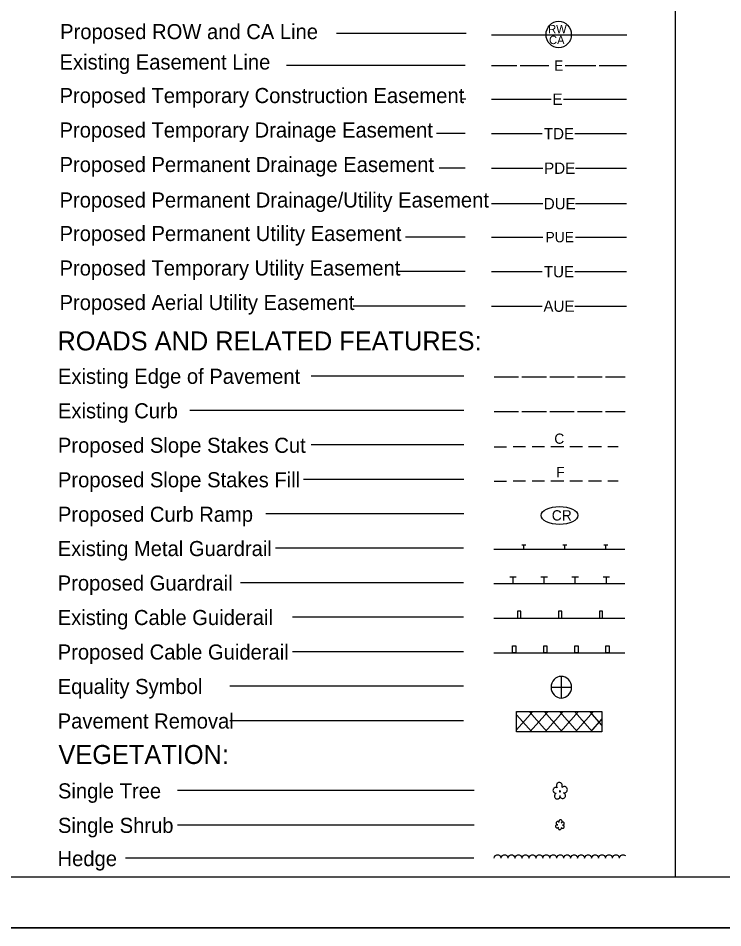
# Model space of a CAD drawing. Extents: x 2025847 to 2026166, y 840763 to 840870.
# Drawn here: x 2026059.3 to 2026094.71, y 840778.42 to 840824.12 of the extents above; entities that cross this region are included whole.
import ezdxf

# ---------------------------------------------------------------- set-up
doc = ezdxf.new("R2010")
doc.units = 0
for name, color, linetype in [('P_RDY_Easement_Permanent_Drainage_Utility', 7, 'Continuous'), ('P_RDY_WCC_CELL', 7, 'Continuous'), ('Sheet_Plan', 7, 'Continuous'), ('Sheet_Plot_Border_Outside_CELL', 7, 'Continuous'), ('Sheet_Symbology', 7, 'Continuous'), ('z - Construction', 7, 'Continuous')]:
    doc.layers.add(name, color=color, linetype=linetype)

msp = doc.modelspace()

# ---------------------------------------------------------------- linework, layer by layer
at = {"layer": 'P_RDY_Easement_Permanent_Drainage_Utility'}
for p, q in [((2026083.088, 840814.806), (2026085.664, 840814.806)), ((2026087.311, 840814.806), (2026089.879, 840814.806))]:
    msp.add_line(p, q, dxfattribs=at)
at = {"layer": 'P_RDY_WCC_CELL'}
msp.add_ellipse((2026086.504, 840799.138), major_axis=(0.923, 0), ratio=0.486807, dxfattribs=at)
at = {"layer": 'Sheet_Plan'}
msp.add_line((2026024.668, 840780.981), (2026164.546, 840780.981), dxfattribs=at)
at = {"layer": 'Sheet_Plot_Border_Outside_CELL'}
msp.add_lwpolyline([(2026023.879, 840870.085), (2026165.546, 840870.085), (2026165.546, 840778.419), (2026023.879, 840778.419)], close=True, dxfattribs=at)
at = {"layer": 'Sheet_Symbology'}
for p, q in [((2026081.82, 840823.354), (2026075.288, 840823.354)), ((2026083.089, 840823.287), (2026089.88, 840823.287)), ((2026081.768, 840821.741), (2026072.775, 840821.741)), ((2026083.088, 840821.741), (2026084.365, 840821.741)), ((2026084.529, 840821.741), (2026085.97, 840821.741)), ((2026086.793, 840821.741), (2026088.336, 840821.741)), ((2026088.501, 840821.741), (2026089.879, 840821.741)), ((2026081.8, 840820.055), (2026081.593, 840820.055)), ((2026083.088, 840820.055), (2026083.303, 840820.055)), ((2026083.303, 840820.055), (2026086.081, 840820.055)), ((2026086.698, 840820.055), (2026089.477, 840820.055)), ((2026089.477, 840820.055), (2026089.879, 840820.055)), ((2026081.768, 840818.322), (2026080.328, 840818.322)), ((2026083.088, 840818.322), (2026083.364, 840818.322)), ((2026083.364, 840818.322), (2026085.627, 840818.322)), ((2026087.274, 840818.322), (2026089.537, 840818.322)), ((2026089.537, 840818.322), (2026089.879, 840818.322)), ((2026081.768, 840816.589), (2026080.45, 840816.589)), ((2026083.088, 840816.589), (2026083.401, 840816.589)), ((2026083.401, 840816.589), (2026085.664, 840816.589)), ((2026087.311, 840816.589), (2026089.574, 840816.589)), ((2026089.574, 840816.589), (2026089.879, 840816.589)), ((2026081.768, 840813.122), (2026078.771, 840813.122)), ((2026083.088, 840813.122), (2026083.404, 840813.122)), ((2026083.404, 840813.122), (2026085.667, 840813.122)), ((2026087.314, 840813.122), (2026089.577, 840813.122)), ((2026089.577, 840813.122), (2026089.879, 840813.122)), ((2026081.768, 840811.389), (2026078.3, 840811.389)), ((2026083.088, 840811.389), (2026083.364, 840811.389)), ((2026083.364, 840811.389), (2026085.627, 840811.389)), ((2026087.274, 840811.389), (2026089.537, 840811.389)), ((2026089.537, 840811.389), (2026089.879, 840811.389)), ((2026081.768, 840809.656), (2026076.133, 840809.656)), ((2026083.088, 840809.656), (2026083.364, 840809.656)), ((2026083.364, 840809.656), (2026085.627, 840809.656)), ((2026087.274, 840809.656), (2026089.537, 840809.656)), ((2026089.537, 840809.656), (2026089.879, 840809.656)), ((2026081.689, 840806.145), (2026074.014, 840806.145)), ((2026083.214, 840806.095), (2026084.449, 840806.095)), ((2026084.614, 840806.095), (2026085.848, 840806.095)), ((2026086.013, 840806.095), (2026087.248, 840806.095)), ((2026087.413, 840806.095), (2026088.647, 840806.095)), ((2026088.812, 840806.095), (2026089.8, 840806.095)), ((2026081.689, 840804.412), (2026067.93, 840804.412)), ((2026083.214, 840804.362), (2026084.449, 840804.362)), ((2026084.614, 840804.362), (2026085.848, 840804.362)), ((2026086.013, 840804.362), (2026087.248, 840804.362)), ((2026087.413, 840804.362), (2026088.647, 840804.362)), ((2026088.812, 840804.362), (2026089.8, 840804.362)), ((2026081.689, 840802.679), (2026074.018, 840802.679)), ((2026083.214, 840802.588), (2026083.84, 840802.588)), ((2026084.803, 840802.588), (2026084.182, 840802.588)), ((2026085.75, 840802.588), (2026085.124, 840802.588)), ((2026086.717, 840802.588), (2026086.075, 840802.588)), ((2026087.659, 840802.588), (2026087.022, 840802.588)), ((2026088.61, 840802.588), (2026087.964, 840802.588)), ((2026089.458, 840802.588), (2026088.931, 840802.588)), ((2026081.689, 840800.946), (2026073.644, 840800.946)), ((2026083.214, 840800.855), (2026083.84, 840800.855)), ((2026084.803, 840800.855), (2026084.182, 840800.855)), ((2026085.75, 840800.855), (2026085.124, 840800.855)), ((2026086.717, 840800.855), (2026086.075, 840800.855)), ((2026087.659, 840800.855), (2026087.022, 840800.855)), ((2026088.61, 840800.855), (2026087.964, 840800.855)), ((2026089.458, 840800.855), (2026088.931, 840800.855)), ((2026081.689, 840799.213), (2026071.735, 840799.213)), ((2026081.676, 840797.49), (2026072.223, 840797.49)), ((2026083.201, 840797.441), (2026089.787, 840797.441)), ((2026084.612, 840797.657), (2026084.818, 840797.657)), ((2026084.715, 840797.441), (2026084.715, 840797.657)), ((2026086.67, 840797.657), (2026086.876, 840797.657)), ((2026086.773, 840797.441), (2026086.773, 840797.657)), ((2026088.728, 840797.657), (2026088.934, 840797.657)), ((2026088.831, 840797.441), (2026088.831, 840797.657)), ((2026084.002, 840796.05), (2026084.331, 840796.05)), ((2026084.167, 840795.708), (2026084.167, 840796.05)), ((2026085.566, 840796.05), (2026085.895, 840796.05)), ((2026085.731, 840795.708), (2026085.731, 840796.05)), ((2026087.13, 840796.05), (2026087.459, 840796.05)), ((2026087.295, 840795.708), (2026087.295, 840796.05)), ((2026088.694, 840796.05), (2026089.023, 840796.05)), ((2026088.859, 840795.708), (2026088.859, 840796.05)), ((2026081.676, 840795.757), (2026070.462, 840795.757)), ((2026089.787, 840795.708), (2026083.201, 840795.708)), ((2026081.676, 840794.024), (2026073.091, 840794.024)), ((2026083.201, 840793.975), (2026089.787, 840793.975)), ((2026081.676, 840792.291), (2026073.091, 840792.291)), ((2026083.201, 840792.242), (2026089.787, 840792.242)), ((2026086.595, 840791.049), (2026086.595, 840790.508)), ((2026081.676, 840790.558), (2026069.936, 840790.558)), ((2026086.081, 840790.508), (2026086.595, 840790.508)), ((2026086.595, 840790.508), (2026086.595, 840789.966)), ((2026086.595, 840790.508), (2026087.109, 840790.508)), ((2026084.35, 840789.284), (2026088.639, 840789.284)), ((2026084.35, 840788.27), (2026084.35, 840789.284)), ((2026084.35, 840789.232), (2026084.395, 840789.284)), ((2026084.35, 840788.369), (2026085.161, 840789.284)), ((2026085.877, 840788.27), (2026084.971, 840789.284)), ((2026085.021, 840788.27), (2026085.926, 840789.284)), ((2026086.638, 840788.27), (2026085.737, 840789.284)), ((2026085.782, 840788.27), (2026086.692, 840789.284)), ((2026087.404, 840788.27), (2026086.498, 840789.284)), ((2026086.548, 840788.27), (2026087.453, 840789.284)), ((2026088.169, 840788.27), (2026087.26, 840789.284)), ((2026087.313, 840788.27), (2026088.215, 840789.284)), ((2026088.639, 840788.595), (2026088.025, 840789.284)), ((2026088.639, 840789.284), (2026088.639, 840788.27)), ((2026081.676, 840788.825), (2026069.936, 840788.825)), ((2026085.111, 840788.27), (2026084.35, 840789.128)), ((2026088.075, 840788.27), (2026088.639, 840788.902)), ((2026088.639, 840788.27), (2026084.35, 840788.27)), ((2026082.218, 840785.312), (2026067.308, 840785.312)), ((2026082.218, 840783.579), (2026067.308, 840783.579)), ((2026082.196, 840781.911), (2026064.688, 840781.911)), ((2026083.216, 840781.911), (2026083.241, 840781.993)), ((2026083.241, 840781.993), (2026083.29, 840782.049)), ((2026083.29, 840782.049), (2026083.356, 840782.088)), ((2026083.356, 840782.088), (2026083.434, 840782.088)), ((2026083.434, 840782.088), (2026083.5, 840782.045)), ((2026083.5, 840782.045), (2026083.545, 840781.989)), ((2026083.545, 840781.989), (2026083.562, 840781.915)), ((2026083.566, 840781.911), (2026083.59, 840781.993)), ((2026083.59, 840781.993), (2026083.64, 840782.049)), ((2026083.64, 840782.049), (2026083.706, 840782.088)), ((2026083.706, 840782.088), (2026083.784, 840782.088)), ((2026083.784, 840782.088), (2026083.85, 840782.045)), ((2026083.85, 840782.045), (2026083.895, 840781.989)), ((2026083.895, 840781.989), (2026083.911, 840781.915)), ((2026083.916, 840781.911), (2026083.94, 840781.993)), ((2026083.94, 840781.993), (2026083.99, 840782.049)), ((2026083.99, 840782.049), (2026084.056, 840782.088)), ((2026084.056, 840782.088), (2026084.134, 840782.088)), ((2026084.134, 840782.088), (2026084.2, 840782.045)), ((2026084.2, 840782.045), (2026084.245, 840781.989)), ((2026084.245, 840781.989), (2026084.261, 840781.915)), ((2026084.265, 840781.911), (2026084.29, 840781.993)), ((2026084.29, 840781.993), (2026084.339, 840782.049)), ((2026084.339, 840782.049), (2026084.405, 840782.088)), ((2026084.405, 840782.088), (2026084.484, 840782.088)), ((2026084.484, 840782.088), (2026084.549, 840782.045)), ((2026084.549, 840782.045), (2026084.595, 840781.989)), ((2026084.595, 840781.989), (2026084.611, 840781.915)), ((2026084.615, 840781.911), (2026084.64, 840781.993)), ((2026084.64, 840781.993), (2026084.689, 840782.049)), ((2026084.689, 840782.049), (2026084.755, 840782.088)), ((2026084.755, 840782.088), (2026084.833, 840782.088)), ((2026084.833, 840782.088), (2026084.899, 840782.045)), ((2026084.899, 840782.045), (2026084.945, 840781.989)), ((2026084.945, 840781.989), (2026084.961, 840781.915)), ((2026084.965, 840781.911), (2026084.99, 840781.993)), ((2026084.99, 840781.993), (2026085.039, 840782.049)), ((2026085.039, 840782.049), (2026085.105, 840782.088)), ((2026085.105, 840782.088), (2026085.183, 840782.088)), ((2026085.183, 840782.088), (2026085.249, 840782.045)), ((2026085.249, 840782.045), (2026085.294, 840781.989)), ((2026085.294, 840781.989), (2026085.311, 840781.915)), ((2026085.315, 840781.911), (2026085.34, 840781.993)), ((2026085.34, 840781.993), (2026085.389, 840782.049)), ((2026085.389, 840782.049), (2026085.455, 840782.088)), ((2026085.455, 840782.088), (2026085.533, 840782.088)), ((2026085.533, 840782.088), (2026085.599, 840782.045)), ((2026085.599, 840782.045), (2026085.644, 840781.989)), ((2026085.644, 840781.989), (2026085.661, 840781.915)), ((2026085.665, 840781.911), (2026085.689, 840781.993)), ((2026085.689, 840781.993), (2026085.739, 840782.049)), ((2026085.739, 840782.049), (2026085.805, 840782.088)), ((2026085.805, 840782.088), (2026085.883, 840782.088)), ((2026085.883, 840782.088), (2026085.949, 840782.045)), ((2026085.949, 840782.045), (2026085.994, 840781.989)), ((2026085.994, 840781.989), (2026086.011, 840781.915)), ((2026086.015, 840781.911), (2026086.039, 840781.993)), ((2026086.039, 840781.993), (2026086.089, 840782.049)), ((2026086.089, 840782.049), (2026086.155, 840782.088)), ((2026086.155, 840782.088), (2026086.233, 840782.088)), ((2026086.233, 840782.088), (2026086.299, 840782.045)), ((2026086.299, 840782.045), (2026086.344, 840781.989)), ((2026086.344, 840781.989), (2026086.36, 840781.915)), ((2026086.364, 840781.911), (2026086.389, 840781.993)), ((2026086.389, 840781.993), (2026086.439, 840782.049)), ((2026086.439, 840782.049), (2026086.504, 840782.088)), ((2026086.504, 840782.088), (2026086.583, 840782.088)), ((2026086.583, 840782.088), (2026086.648, 840782.045)), ((2026086.648, 840782.045), (2026086.694, 840781.989)), ((2026086.694, 840781.989), (2026086.71, 840781.915)), ((2026086.714, 840781.911), (2026086.739, 840781.993)), ((2026086.739, 840781.993), (2026086.788, 840782.049)), ((2026086.788, 840782.049), (2026086.854, 840782.088)), ((2026086.854, 840782.088), (2026086.932, 840782.088)), ((2026086.932, 840782.088), (2026086.998, 840782.045)), ((2026086.998, 840782.045), (2026087.044, 840781.989)), ((2026087.044, 840781.989), (2026087.06, 840781.915)), ((2026087.064, 840781.911), (2026087.089, 840781.993)), ((2026087.089, 840781.993), (2026087.138, 840782.049)), ((2026087.138, 840782.049), (2026087.204, 840782.088)), ((2026087.204, 840782.088), (2026087.282, 840782.088)), ((2026087.282, 840782.088), (2026087.348, 840782.045)), ((2026087.348, 840782.045), (2026087.393, 840781.989)), ((2026087.393, 840781.989), (2026087.41, 840781.915)), ((2026087.414, 840781.911), (2026087.439, 840781.993)), ((2026087.439, 840781.993), (2026087.488, 840782.049)), ((2026087.488, 840782.049), (2026087.554, 840782.088)), ((2026087.554, 840782.088), (2026087.632, 840782.088)), ((2026087.632, 840782.088), (2026087.698, 840782.045)), ((2026087.698, 840782.045), (2026087.743, 840781.989)), ((2026087.743, 840781.989), (2026087.76, 840781.915)), ((2026087.764, 840781.911), (2026087.789, 840781.993)), ((2026087.789, 840781.993), (2026087.838, 840782.049)), ((2026087.838, 840782.049), (2026087.904, 840782.088)), ((2026087.904, 840782.088), (2026087.982, 840782.088)), ((2026087.982, 840782.088), (2026088.048, 840782.045)), ((2026088.048, 840782.045), (2026088.093, 840781.989)), ((2026088.093, 840781.989), (2026088.11, 840781.915)), ((2026088.114, 840781.911), (2026088.138, 840781.993)), ((2026088.138, 840781.993), (2026088.188, 840782.049)), ((2026088.188, 840782.049), (2026088.254, 840782.088)), ((2026088.254, 840782.088), (2026088.332, 840782.088)), ((2026088.332, 840782.088), (2026088.398, 840782.045)), ((2026088.398, 840782.045), (2026088.443, 840781.989)), ((2026088.443, 840781.989), (2026088.459, 840781.915)), ((2026088.464, 840781.911), (2026088.488, 840781.993)), ((2026088.488, 840781.993), (2026088.538, 840782.049)), ((2026088.538, 840782.049), (2026088.604, 840782.088)), ((2026088.604, 840782.088), (2026088.682, 840782.088)), ((2026088.682, 840782.088), (2026088.748, 840782.045)), ((2026088.748, 840782.045), (2026088.793, 840781.989)), ((2026088.793, 840781.989), (2026088.809, 840781.915)), ((2026088.813, 840781.911), (2026088.838, 840781.993)), ((2026088.838, 840781.993), (2026088.887, 840782.049)), ((2026088.887, 840782.049), (2026088.953, 840782.088)), ((2026088.953, 840782.088), (2026089.032, 840782.088)), ((2026089.032, 840782.088), (2026089.097, 840782.045)), ((2026089.097, 840782.045), (2026089.143, 840781.989)), ((2026089.143, 840781.989), (2026089.159, 840781.915)), ((2026089.163, 840781.911), (2026089.188, 840781.993)), ((2026089.188, 840781.993), (2026089.237, 840782.049)), ((2026089.237, 840782.049), (2026089.303, 840782.088)), ((2026089.303, 840782.088), (2026089.381, 840782.088)), ((2026089.381, 840782.088), (2026089.447, 840782.045)), ((2026089.447, 840782.045), (2026089.493, 840781.989)), ((2026089.493, 840781.989), (2026089.509, 840781.915)), ((2026089.513, 840781.911), (2026089.538, 840781.993)), ((2026089.538, 840781.993), (2026089.587, 840782.049)), ((2026089.587, 840782.049), (2026089.653, 840782.088)), ((2026089.653, 840782.088), (2026089.731, 840782.088)), ((2026089.731, 840782.088), (2026089.797, 840782.045)), ((2026089.797, 840782.045), (2026089.801, 840782.041))]:
    msp.add_line(p, q, dxfattribs=at)
for points in [[(2026084.393, 840793.975), (2026084.558, 840793.975), (2026084.558, 840794.321), (2026084.393, 840794.321)], [(2026086.451, 840793.975), (2026086.616, 840793.975), (2026086.616, 840794.321), (2026086.451, 840794.321)], [(2026088.509, 840793.975), (2026088.673, 840793.975), (2026088.673, 840794.321), (2026088.509, 840794.321)], [(2026084.145, 840792.588), (2026084.31, 840792.588), (2026084.31, 840792.242), (2026084.145, 840792.242)], [(2026085.709, 840792.588), (2026085.874, 840792.588), (2026085.874, 840792.242), (2026085.709, 840792.242)], [(2026087.273, 840792.588), (2026087.438, 840792.588), (2026087.438, 840792.242), (2026087.273, 840792.242)], [(2026088.837, 840792.588), (2026089.002, 840792.588), (2026089.002, 840792.242), (2026088.837, 840792.242)]]:
    msp.add_lwpolyline(points, close=True, dxfattribs=at)
for points in [[(2026086.625, 840785.493), (2026086.638, 840785.524), (2026086.644, 840785.555), (2026086.641, 840785.589), (2026086.634, 840785.619), (2026086.618, 840785.65), (2026086.602, 840785.674), (2026086.576, 840785.698), (2026086.55, 840785.711), (2026086.518, 840785.722), (2026086.488, 840785.722), (2026086.456, 840785.718), (2026086.427, 840785.708), (2026086.401, 840785.691), (2026086.378, 840785.667), (2026086.362, 840785.64), (2026086.349, 840785.609), (2026086.346, 840785.579), (2026086.346, 840785.544), (2026086.352, 840785.514), (2026086.365, 840785.483), (2026086.385, 840785.456), (2026086.359, 840785.469), (2026086.33, 840785.476), (2026086.3, 840785.473), (2026086.271, 840785.466), (2026086.245, 840785.452), (2026086.219, 840785.432), (2026086.203, 840785.408), (2026086.187, 840785.381), (2026086.181, 840785.353), (2026086.177, 840785.319), (2026086.181, 840785.288), (2026086.194, 840785.261), (2026086.21, 840785.234), (2026086.229, 840785.213), (2026086.255, 840785.196), (2026086.281, 840785.183), (2026086.31, 840785.179), (2026086.339, 840785.179), (2026086.313, 840785.166), (2026086.291, 840785.145), (2026086.275, 840785.121), (2026086.262, 840785.091), (2026086.255, 840785.06), (2026086.252, 840785.029), (2026086.258, 840784.999), (2026086.271, 840784.971), (2026086.288, 840784.944), (2026086.307, 840784.923), (2026086.333, 840784.906), (2026086.362, 840784.896), (2026086.391, 840784.893), (2026086.42, 840784.896), (2026086.45, 840784.903), (2026086.476, 840784.92), (2026086.498, 840784.941), (2026086.514, 840784.964), (2026086.527, 840784.992), (2026086.534, 840785.022)], [(2026086.524, 840785.06), (2026086.527, 840785.026), (2026086.537, 840784.995), (2026086.553, 840784.968), (2026086.576, 840784.944), (2026086.602, 840784.927), (2026086.631, 840784.917), (2026086.663, 840784.913), (2026086.693, 840784.917), (2026086.722, 840784.927), (2026086.748, 840784.944), (2026086.77, 840784.964), (2026086.79, 840784.992), (2026086.8, 840785.022), (2026086.806, 840785.053), (2026086.803, 840785.087), (2026086.796, 840785.118), (2026086.78, 840785.149), (2026086.761, 840785.173), (2026086.735, 840785.19), (2026086.706, 840785.203), (2026086.738, 840785.2), (2026086.77, 840785.2), (2026086.8, 840785.21), (2026086.829, 840785.224), (2026086.855, 840785.244), (2026086.874, 840785.271), (2026086.89, 840785.302), (2026086.897, 840785.333), (2026086.9, 840785.367), (2026086.894, 840785.401), (2026086.884, 840785.432), (2026086.864, 840785.459), (2026086.842, 840785.483), (2026086.816, 840785.5), (2026086.783, 840785.514), (2026086.754, 840785.517), (2026086.722, 840785.517), (2026086.689, 840785.507), (2026086.663, 840785.49), (2026086.638, 840785.469)], [(2026086.534, 840785.302), (2026086.521, 840785.302), (2026086.508, 840785.299), (2026086.501, 840785.288), (2026086.498, 840785.275), (2026086.501, 840785.261), (2026086.511, 840785.251), (2026086.524, 840785.251), (2026086.537, 840785.254), (2026086.547, 840785.265), (2026086.55, 840785.278), (2026086.544, 840785.292), (2026086.534, 840785.302)], [(2026086.485, 840783.706), (2026086.476, 840783.726), (2026086.456, 840783.743), (2026086.437, 840783.757), (2026086.414, 840783.76), (2026086.391, 840783.757), (2026086.369, 840783.75), (2026086.349, 840783.733), (2026086.336, 840783.712), (2026086.33, 840783.689), (2026086.33, 840783.665), (2026086.336, 840783.641), (2026086.349, 840783.62), (2026086.369, 840783.603), (2026086.391, 840783.593), (2026086.414, 840783.593), (2026086.391, 840783.596), (2026086.369, 840783.596), (2026086.349, 840783.59), (2026086.33, 840783.576), (2026086.317, 840783.559), (2026086.31, 840783.538), (2026086.307, 840783.515), (2026086.31, 840783.491), (2026086.32, 840783.47), (2026086.336, 840783.453), (2026086.356, 840783.443), (2026086.375, 840783.436), (2026086.398, 840783.44), (2026086.417, 840783.446), (2026086.437, 840783.46), (2026086.45, 840783.477), (2026086.44, 840783.453), (2026086.437, 840783.429), (2026086.443, 840783.405), (2026086.453, 840783.385), (2026086.469, 840783.364), (2026086.488, 840783.354), (2026086.511, 840783.347), (2026086.534, 840783.351), (2026086.557, 840783.358), (2026086.576, 840783.371), (2026086.589, 840783.392), (2026086.599, 840783.416), (2026086.599, 840783.44), (2026086.595, 840783.463), (2026086.605, 840783.446), (2026086.625, 840783.429), (2026086.644, 840783.422), (2026086.667, 840783.419), (2026086.689, 840783.422), (2026086.709, 840783.433), (2026086.725, 840783.45), (2026086.735, 840783.47), (2026086.738, 840783.494), (2026086.738, 840783.518), (2026086.728, 840783.538), (2026086.715, 840783.556), (2026086.699, 840783.569), (2026086.676, 840783.579), (2026086.654, 840783.579), (2026086.676, 840783.579), (2026086.699, 840783.586), (2026086.715, 840783.6), (2026086.732, 840783.62), (2026086.738, 840783.641), (2026086.738, 840783.665), (2026086.735, 840783.689), (2026086.722, 840783.709), (2026086.706, 840783.723), (2026086.683, 840783.733), (2026086.66, 840783.736), (2026086.641, 840783.73), (2026086.618, 840783.719), (2026086.605, 840783.702), (2026086.595, 840783.682)], [(2026086.586, 840783.682), (2026086.605, 840783.692), (2026086.621, 840783.712), (2026086.631, 840783.733), (2026086.634, 840783.757), (2026086.634, 840783.781), (2026086.625, 840783.804), (2026086.612, 840783.822), (2026086.595, 840783.839), (2026086.573, 840783.846), (2026086.55, 840783.849), (2026086.527, 840783.846), (2026086.508, 840783.835), (2026086.488, 840783.818), (2026086.479, 840783.798), (2026086.472, 840783.774), (2026086.472, 840783.75), (2026086.476, 840783.726), (2026086.488, 840783.706)]]:
    msp.add_lwpolyline(points, dxfattribs=at)
msp.add_ellipse((2026086.463, 840823.3), major_axis=(0, 0.669), ratio=0.95, dxfattribs=at)
for major_axis, start_param, end_param in [((0, 0.542), 6.283087, 7.853963), ((0, 0.542), 4.712291, 6.283167), ((0, -0.542), 4.712291, 6.283167), ((0, -0.542), 6.283087, 7.853963)]:
    msp.add_ellipse((2026086.595, 840790.507), major_axis=major_axis, ratio=0.95, start_param=start_param, end_param=end_param, dxfattribs=at)
at = {"layer": 'z - Construction'}
for p, q in [((2026092.318, 840869.009), (2026092.316, 840780.981)), ((2026023.879, 840778.419), (2026165.546, 840778.419))]:
    msp.add_line(p, q, dxfattribs=at)

# ---------------------------------------------------------------- texts
at = {"layer": 'P_RDY_Easement_Permanent_Drainage_Utility'}
msp.add_text('DUE', height=0.5675, dxfattribs=at).set_placement((2026085.714, 840814.52))
at = {"layer": 'P_RDY_WCC_CELL'}
msp.add_text('CR', height=0.5199, dxfattribs=at).set_placement((2026086.116, 840798.882))
at = {"layer": 'Sheet_Symbology'}
for s, height, p in [('Proposed ROW and CA Line', 0.75818, (2026061.404, 840823.07)), ('RW', 0.4192, (2026085.932, 840823.367)), ('CA', 0.4192, (2026085.978, 840822.822)), ('Existing Easement Line', 0.75818, (2026061.374, 840821.545)), ('E', 0.52, (2026086.233, 840821.481)), ('Proposed Temporary Construction Easement', 0.75818, (2026061.374, 840819.859)), ('E', 0.568, (2026086.151, 840819.769)), ('Proposed Temporary Drainage Easement', 0.75818, (2026061.374, 840818.126)), ('TDE', 0.5675, (2026085.719, 840818.036)), ('Proposed Permanent Drainage Easement', 0.75818, (2026061.374, 840816.393)), ('PDE', 0.5675, (2026085.734, 840816.303)), ('Proposed Permanent Drainage/Utility Easement', 0.75818, (2026061.374, 840814.61)), ('Proposed Permanent Utility Easement', 0.75818, (2026061.374, 840812.926)), ('PUE', 0.5199, (2026085.8, 840812.863)), ('Proposed Temporary Utility Easement', 0.75818, (2026061.374, 840811.193)), ('TUE', 0.5675, (2026085.719, 840811.104)), ('Proposed Aerial Utility Easement', 0.75818, (2026061.374, 840809.46)), ('AUE', 0.5675, (2026085.697, 840809.371)), ('ROADS AND RELATED FEATURES:', 0.95314, (2026061.27, 840807.431)), ('Existing Edge of Pavement', 0.75818, (2026061.295, 840805.751)), ('Existing Curb', 0.75818, (2026061.295, 840804.018)), ('Proposed Slope Stakes Cut', 0.75818, (2026061.295, 840802.285)), ('C', 0.514, (2026086.244, 840802.739)), ('F', 0.514, (2026086.342, 840801.06)), ('Proposed Slope Stakes Fill', 0.75818, (2026061.295, 840800.552)), ('Proposed Curb Ramp', 0.75818, (2026061.295, 840798.819)), ('Existing Metal Guardrail', 0.75818, (2026061.282, 840797.096)), ('Proposed Guardrail', 0.75818, (2026061.283, 840795.364)), ('Existing Cable Guiderail', 0.75818, (2026061.283, 840793.631)), ('Proposed Cable Guiderail', 0.75818, (2026061.283, 840791.898)), ('Equality Symbol', 0.75818, (2026061.283, 840790.165)), ('Pavement Removal', 0.75818, (2026061.283, 840788.432)), ('VEGETATION:', 0.95314, (2026061.319, 840786.651)), ('Single Tree', 0.75818, (2026061.296, 840784.92)), ('Single Shrub', 0.75818, (2026061.296, 840783.187)), ('Hedge', 0.7582, (2026061.274, 840781.519))]:
    msp.add_text(s, height=height, dxfattribs=at).set_placement(p)

doc.saveas('drawing.dxf')
